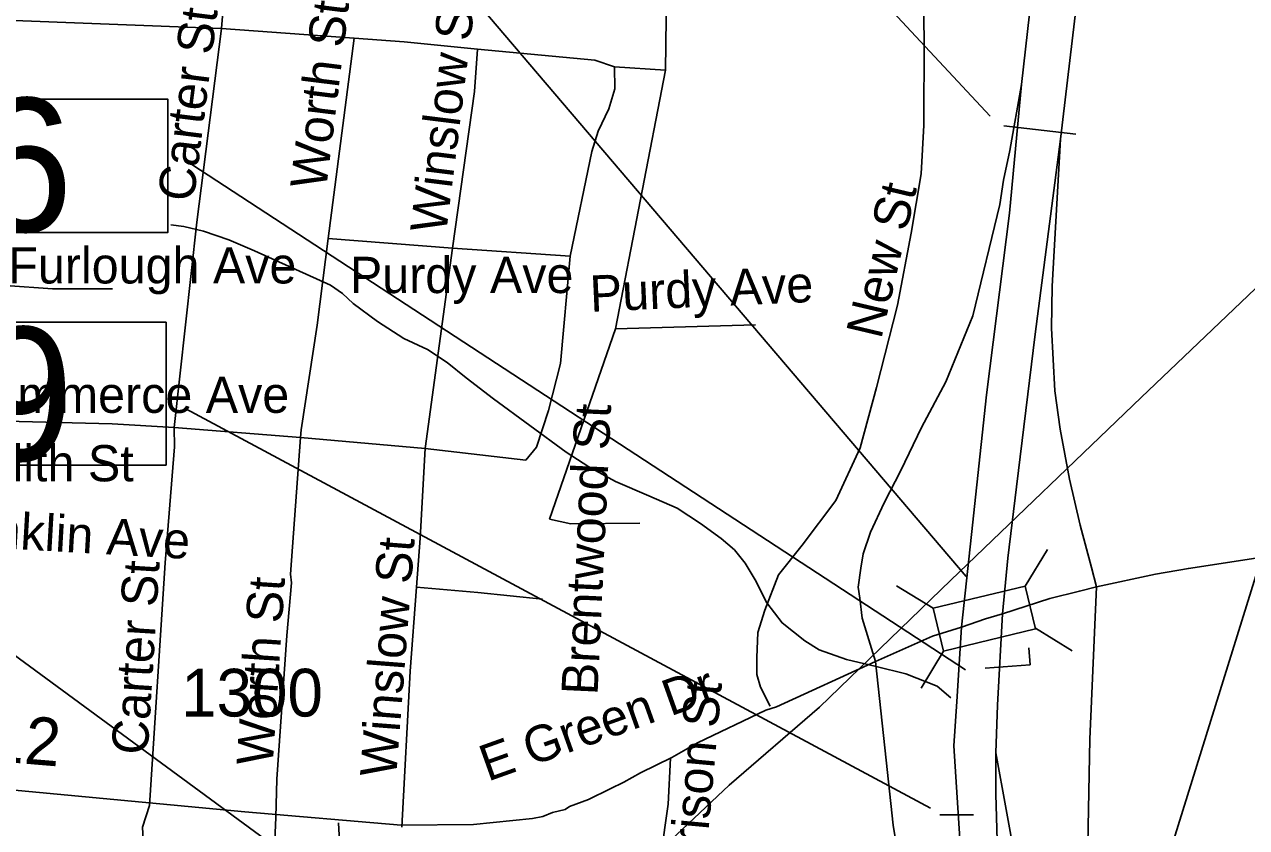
# Model space of a CAD drawing. Extents: x 1662474 to 1856135, y 779280 to 917889.
# Drawn here: x 1708754 to 1711959, y 803240 to 805345 of the extents above; entities that cross this region are included whole.
import ezdxf

# ---------------------------------------------------------------- set-up
doc = ezdxf.new("R2010")
doc.units = 0
for name, color, linetype in [('Exist Hydrographic Misc Water Feature', 7, 'Continuous'), ('Exist Road Non-System Type 51', 7, 'Continuous'), ('Exist Road Non-System Type 51 Label', 7, 'Continuous'), ('Exist Road Primary Interstate Structure Cantilever Sign CELL', 7, 'Continuous'), ('Exist Road Primary Interstate Structure Cantilever Sign Number Label', 7, 'Continuous'), ('Exist Road Primary US Divided Attributed', 7, 'Continuous'), ('Exist Road Primary US Ramp 1 Lane  Attributed', 7, 'Continuous'), ('Exist Road Primary US Structure Ovrhead Sign CELL', 7, 'Continuous'), ('Exist Road Primary US Structure Standard Bridge Number Label', 7, 'Continuous'), ('Exist Road Secondary Mileage Tenths English Label', 7, 'Continuous'), ('Exist Road Secondary Structure Standard Bridge CELL', 7, 'Continuous'), ('Exist Road Secondary Structure Standard Bridge Number Label', 7, 'Continuous'), ('Exist Road Secondary Type 51 Label', 7, 'Continuous'), ('Exist Road Secondary Type 51 Number Label', 7, 'Continuous'), ('Exist Road Secondary Type 51 Undivided 4 Lane Attributed', 7, 'Continuous'), ('Exist Utilities Electrical Transmission Line', 7, 'Continuous')]:
    doc.layers.add(name, color=color, linetype=linetype)

msp = doc.modelspace()

# ---------------------------------------------------------------- linework, layer by layer
at = {"layer": 'Exist Hydrographic Misc Water Feature'}
msp.add_lwpolyline([(1711182.9, 803580.1), (1711147.1, 803610.4), (1711065.5, 803643.3), (1710987.6, 803662), (1710909.8, 803680.7), (1710838, 803705.4), (1710800.3, 803729.8), (1710740.6, 803776.3), (1710701.1, 803828.7), (1710669.8, 803889.1), (1710644.1, 803933.3), (1710616.3, 803967.6), (1710580.8, 803997.9), (1710527, 804036.5), (1710465.4, 804077), (1710391.7, 804109.7), (1710304.1, 804146.6), (1710234.3, 804185.3), (1710174.8, 804223.9), (1709984, 804363.7), (1709912.5, 804418.3), (1709862.9, 804458.8), (1709811.1, 804493.3), (1709749.4, 804522), (1709679.8, 804566.6), (1709616.2, 804613.3), (1709588.5, 804639.5), (1709556.6, 804661.8), (1709357.5, 804751.8), (1709289.8, 804780.4), (1709223.8, 804803), (1709172, 804815.5), (1709138, 804819.9)], dxfattribs=at)
at = {"layer": 'Exist Road Non-System Type 51'}
for p, q in [((1708396.1, 805367.9), (1709271.1, 805334.2)), ((1709271.1, 805334.2), (1709618.6, 805308.8)), ((1709618.6, 805308.8), (1709550.6, 804784.1)), ((1710301.6, 805233.4), (1710435.5, 805224.8)), ((1710435.5, 805224.8), (1710304.2, 804547.4)), ((1709550.6, 804784.1), (1709876.6, 804758.4)), ((1709876.6, 804758.4), (1709805, 804233.8)), ((1709876.6, 804758.4), (1710184.9, 804737.7)), ((1710304.2, 804547.4), (1710130.5, 804048.7)), ((1710304.2, 804547.4), (1710671.1, 804557.6)), ((1709146.8, 804288.4), (1709478.2, 804261.9)), ((1709478.2, 804261.9), (1709452.2, 803904.4)), ((1709478.2, 804261.9), (1709805, 804233.8)), ((1709123.4, 803933.8), (1709081.9, 803298.1)), ((1709413.1, 803266), (1709394.9, 802824.4))]:
    msp.add_line(p, q, dxfattribs=at)
for points in [[(1709381.6, 805799.9), (1709332.1, 805729), (1709301.6, 805661.5), (1709290.9, 805581.5), (1709271.1, 805334.2)], [(1710444.1, 805726.9), (1710438.4, 805453.7), (1710437, 805360.2), (1710435.5, 805224.8)], [(1711106.1, 805675.9), (1711113.1, 805305.9), (1711112.4, 805080.7), (1711105, 804952.9), (1711079.2, 804798), (1711043.1, 804609.4), (1710988.1, 804393), (1710945.1, 804235), (1710881.6, 804097.5), (1710793.5, 803979.7), (1710731.5, 803902.2), (1710695.4, 803809.4), (1710677.4, 803751.6), (1710674.9, 803685.7), (1710674.6, 803641.1), (1710684.2, 803607.8), (1710709.8, 803557.9)], [(1709271.1, 805334.2), (1709206.6, 804826.7), (1709146.8, 804288.4)], [(1709618.6, 805308.8), (1709749.6, 805299.4), (1709942.4, 805280.2)], [(1709942.4, 805280.2), (1709933.9, 805168.6), (1709876.6, 804758.4)], [(1709942.4, 805280.2), (1710249.6, 805251), (1710301.6, 805233.4)], [(1710301.6, 805233.4), (1710302.1, 805175.7), (1710286.9, 805124), (1710258.9, 805065.2), (1710242, 805012.2), (1710184.9, 804737.7)], [(1709550.6, 804784.1), (1709521.4, 804556.6), (1709479.6, 804282.6), (1709478.2, 804261.9)], [(1709805, 804233.8), (1710068.5, 804202.5), (1710096.9, 804236.9), (1710128.4, 804333.2), (1710159.6, 804455.8), (1710184.9, 804737.7)], [(1708456.8, 804677.9), (1708827.4, 804652.1), (1708984.9, 804651.9)], [(1708425.5, 804311.7), (1708984.4, 804297.8), (1709146.8, 804288.4)], [(1709146.8, 804288.4), (1709147.6, 804237.9), (1709123.4, 803933.8)], [(1709805, 804233.8), (1709792.1, 803998.6), (1709782.1, 803869.9)], [(1710130.5, 804048.7), (1710186.9, 804036.4), (1710367.8, 804037.7)], [(1709452.2, 803904.4), (1709454.4, 803881.2), (1709441.8, 803743.2), (1709416.1, 803366.9), (1709413.1, 803266)], [(1709782.1, 803869.9), (1709765.9, 803650.2), (1709743.6, 803241.1)], [(1709782.1, 803869.9), (1709942.9, 803855.8), (1710112.9, 803838.4)], [(1710447.9, 803422.2), (1710441.8, 803301.4), (1710422.4, 803165.8), (1710417.4, 803048.4), (1710407.4, 802967.6)], [(1709081.9, 803298.1), (1709063.9, 803241.1), (1709099.2, 802544.5), (1709098.5, 802517.5)], [(1709577.8, 803252.4), (1709579.6, 803220.4), (1709576.4, 802843.2)]]:
    msp.add_lwpolyline(points, dxfattribs=at)
at = {"layer": 'Exist Road Primary Interstate Structure Cantilever Sign CELL'}
for q in [(1711387.7, 803711.2), (1711273.3, 803658.2)]:
    msp.add_line((1711391, 803666.9), q, dxfattribs=at)
at = {"layer": 'Exist Road Primary Interstate Structure Cantilever Sign Number Label'}
msp.add_line((1711221.9, 803653.2), (1709193.2, 804977.8), dxfattribs=at)
msp.add_lwpolyline([(1707567.4, 805148.6), (1709130.3, 805148.6), (1709130.3, 804799.6), (1707567.4, 804799.6)], close=True, dxfattribs=at)
at = {"layer": 'Exist Road Primary US Divided Attributed'}
for points in [[(1711475.8, 806175.9), (1711465, 806069.9), (1711440.2, 805814.7), (1711405.4, 805512.4), (1711368.9, 805187.2)], [(1711590.8, 806156.2), (1711560.3, 805844.6), (1711537.9, 805612.3), (1711470.5, 805043.7)], [(1711368.9, 805187.2), (1711337.4, 804849.8), (1711276.4, 804373.9), (1711237.1, 804007.8), (1711211.1, 803765.4)], [(1711470.5, 805043.7), (1711404.3, 804533.5), (1711355.1, 804133.1), (1711333, 803946.4), (1711318.8, 803800.5)], [(1711318.8, 803800.5), (1711305.5, 803560.5), (1711301.1, 803436.1), (1711301.1, 803327.2), (1711305.5, 803176.2), (1711318.8, 803014), (1711336.6, 802856.3), (1711368.8, 802635.3), (1711417.7, 802399.9), (1711457.7, 802208.9), (1711493.3, 802088.9), (1711518.9, 801984.3), (1711569.6, 801828.6), (1711603.5, 801730.5), (1711681.4, 801524.1)], [(1711211.1, 803765.4), (1711198.6, 803570.1), (1711190.8, 803454.6), (1711220.2, 803008.1)]]:
    msp.add_lwpolyline(points, dxfattribs=at)
at = {"layer": 'Exist Road Primary US Ramp 1 Lane  Attributed'}
for points in [[(1711368.9, 805187.2), (1711338.3, 805014.6), (1711321.7, 804936.7), (1711311.8, 804872.9), (1711240.9, 804581), (1711169.7, 804408.6), (1711106.7, 804288.2), (1711052, 804175.9), (1711008.1, 804091.1), (1710972.5, 804014.4), (1710953.4, 803957), (1710947, 803919.6), (1710939.9, 803869.9), (1710944.9, 803840.9), (1710951.1, 803789.1), (1710985.6, 803675.5)], [(1711470.5, 805043.7), (1711448.5, 804659.3), (1711447.1, 804548.6), (1711455.5, 804384.5), (1711470.2, 804284.3), (1711494.3, 804153.2), (1711522.3, 804032.4), (1711551.8, 803921.8), (1711565.4, 803870.9)], [(1711565.4, 803870.9), (1711547.8, 803471.6), (1711538, 802965.7), (1711531.9, 802624.8)], [(1710985.6, 803675.5), (1711014, 803416.7), (1711032, 803246.2), (1711042.1, 803182.8), (1711056.5, 803096.3), (1711070.2, 802942.9), (1711070.2, 802715.2), (1711062.2, 802537.7), (1711059.6, 802451.8), (1711064.8, 802363.2), (1711075.2, 802282.5), (1711093.5, 802212.2), (1711137.8, 802076.8)], [(1711301.1, 803436.1), (1711355.1, 803138.7), (1711417.1, 802936.3), (1711482.4, 802760), (1711531.9, 802624.8)]]:
    msp.add_lwpolyline(points, dxfattribs=at)
at = {"layer": 'Exist Road Primary US Structure Ovrhead Sign CELL'}
for p, q in [((1711286.3, 805104.5), (1709637.3, 806874)), ((1711322.2, 805078.9), (1711510.6, 805057.1)), ((1711129.5, 803291.3), (1709177.6, 804337.6)), ((1711154.2, 803273.7), (1711242.7, 803273.7))]:
    msp.add_line(p, q, dxfattribs=at)
msp.add_lwpolyline([(1707545.7, 804564.1), (1709125.7, 804564.1), (1709125.7, 804190), (1707545.7, 804190)], close=True, dxfattribs=at)
at = {"layer": 'Exist Road Primary US Structure Standard Bridge Number Label'}
for p, q in [((1711617.2, 802724.1), (1712522.7, 805636.8)), ((1710930.6, 802076.4), (1708656.2, 803744.8))]:
    msp.add_line(p, q, dxfattribs=at)
at = {"layer": 'Exist Road Secondary Structure Standard Bridge CELL'}
for p, q in [((1711378.2, 803872.5), (1711437.1, 803969.1)), ((1711040.5, 803873.6), (1711137.2, 803814.6)), ((1711404.9, 803762.5), (1711501.5, 803703.6)), ((1711105.5, 803605.5), (1711164.4, 803702.1))]:
    msp.add_line(p, q, dxfattribs=at)
msp.add_lwpolyline([(1711137.2, 803814.6), (1711378.1, 803873), (1711405.3, 803760.5), (1711164.4, 803702.1)], close=True, dxfattribs=at)
at = {"layer": 'Exist Road Secondary Structure Standard Bridge Number Label'}
msp.add_line((1711223.3, 803897.7), (1708975.9, 806535.5), dxfattribs=at)
at = {"layer": 'Exist Road Secondary Type 51 Undivided 4 Lane Attributed'}
for points in [[(1711565.4, 803870.9), (1711719.9, 803903.9), (1711806.1, 803919), (1712017.4, 803951.3), (1712198.4, 803966.4), (1712302.4, 803975.2), (1712392.2, 803978.5), (1712457.1, 803977.2), (1712505.7, 803975.8), (1712588.9, 803973.7), (1712659.7, 803968.6), (1712709.3, 803968.6), (1712825.7, 803957.8), (1713072.4, 803936.3), (1713810.8, 803901.7)], [(1711318.8, 803800.5), (1711443, 803840.2), (1711520.3, 803860), (1711565.4, 803870.9)], [(1711211.1, 803765.4), (1711273.8, 803786.9), (1711318.8, 803800.5)], [(1710985.6, 803675.5), (1711135.1, 803741.3), (1711211.1, 803765.4)], [(1710985.6, 803675.5), (1710725.9, 803556.2), (1710698, 803547.5), (1710519.2, 803462.1), (1710452.1, 803424), (1710369.6, 803383.1), (1710325.6, 803359.1), (1710289.6, 803341.2), (1710233.6, 803313.2), (1710183.6, 803295.2), (1710171.6, 803287.2), (1710138.7, 803279.3), (1710113.7, 803269.2), (1710086.1, 803264.2), (1709931.9, 803248.2), (1709742.2, 803246.6), (1709331.9, 803280.9), (1707093.6, 803491.7), (1706412.3, 803544.3)]]:
    msp.add_lwpolyline(points, dxfattribs=at)
at = {"layer": 'Exist Utilities Electrical Transmission Line'}
msp.add_lwpolyline([(1708361.1, 801237.7), (1708802.7, 801651.1), (1709070.2, 801905.3), (1709757.3, 802555.4), (1710602.2, 803351), (1710839.1, 803555.2), (1711183.6, 803888.6), (1711682.4, 804367.2), (1712000.4, 804670.6), (1712495, 805135.2), (1713050.2, 805659.3), (1713449.3, 806029.3), (1713779.5, 806348.5), (1714124.4, 806683.5), (1714460.6, 806996.7), (1714551.9, 807077.2), (1714763.8, 807525.9), (1714928.9, 807877.4), (1715065, 808165.4), (1715330.2, 808405.6), (1715755.5, 808789.2), (1716106.2, 809133.9), (1716438.8, 809461.3)], dxfattribs=at)

# ---------------------------------------------------------------- texts
at = {"layer": 'Exist Road Non-System Type 51 Label'}
for s, rotation, p in [('Worth St', 82.9523, (1709545.1, 804910.3)), ('Winslow St', 82.8585, (1709859.7, 804794.6)), ('Carter St', 82.8438, (1709197.6, 804877.7)), ('New St', 76.72, (1711000.4, 804517.6)), ('Purdy Ave', 2.5606, (1710238.7, 804591.6)), ('Brentwood St', 87.3178, (1710256.8, 803585.9)), ('Franklin Ave', 356.7192, (1708481.1, 803984.1)), ('Winslow St', 85.5676, (1709728.7, 803370)), ('Carter St', 86.4129, (1709077, 803429)), ('Worth St', 86.2667, (1709405.1, 803400.6)), ('Garrison St', 84.8086, (1710524.9, 802979))]:
    msp.add_text(s, height=95, rotation=rotation, dxfattribs=at).set_placement(p)
for s, p in [('Furlough Ave', (1708711.8, 804665.9)), ('Purdy Ave', (1709607.6, 804640.8)), ('E Commerce Ave', (1708453.2, 804326.9)), ('Meredith St', (1708391.1, 804147.4))]:
    msp.add_text(s, height=95, dxfattribs=at).set_placement(p)
at = {"layer": 'Exist Road Primary Interstate Structure Cantilever Sign Number Label'}
msp.add_text('L1076', height=350, dxfattribs=at).set_placement((1707579.9, 804801.7))
at = {"layer": 'Exist Road Primary US Structure Ovrhead Sign CELL'}
msp.add_text('S1089', height=350, dxfattribs=at).set_placement((1707529.6, 804201.6))
at = {"layer": 'Exist Road Secondary Mileage Tenths English Label'}
msp.add_text('2.12', height=125, rotation=355.2314, dxfattribs=at).set_placement((1708519.6, 803427.1))
at = {"layer": 'Exist Road Secondary Type 51 Label'}
msp.add_text('E Green Dr', height=95, rotation=19.6643, dxfattribs=at).set_placement((1709969.2, 803360.1))
at = {"layer": 'Exist Road Secondary Type 51 Number Label'}
msp.add_text('1300', height=125, dxfattribs=at).set_placement((1709164.9, 803531.1))

doc.saveas('drawing.dxf')
